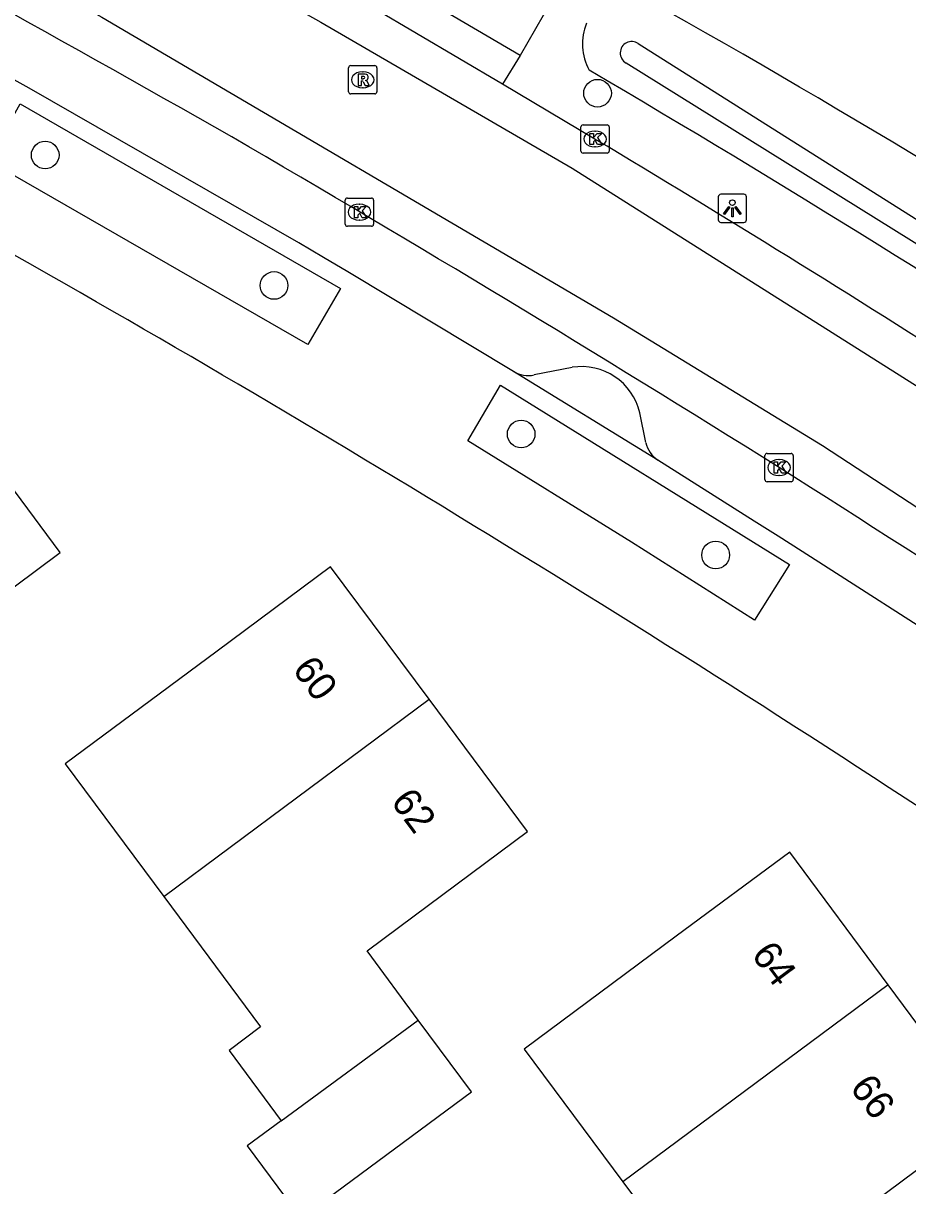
# Model space of a CAD drawing. Extents: x 163427 to 164190, y 380331 to 381641.
# Drawn here: x 163782.5 to 163813.78, y 381420.94 to 381462.05 of the extents above; entities that cross this region are included whole.
import ezdxf

# ---------------------------------------------------------------- set-up
doc = ezdxf.new("R2010")
doc.units = 0
for name, color, linetype in [('IMGEO_Boom', 7, 'Continuous'), ('IMGEO_Erf', 7, 'Continuous'), ('IMGEO_Groenvoorziening', 7, 'Continuous'), ('IMGEO_Kolk', 7, 'Continuous'), ('IMGEO_Lichtpunt', 7, 'Continuous'), ('IMGEO_Pand', 7, 'Continuous'), ('IMGEO_Pand_nummerreeks', 7, 'Continuous'), ('IMGEO_Parkeervlak_open', 7, 'Continuous'), ('IMGEO_Rijbaan_lokaal_gesloten', 7, 'Continuous'), ('IMGEO_Rioolput', 7, 'Continuous'), ('IMGEO_Voetpad_open', 7, 'Continuous'), ('IMGEO_Waterloop', 7, 'Continuous')]:
    doc.layers.add(name, color=color, linetype=linetype)

msp = doc.modelspace()

# ---------------------------------------------------------------- linework, layer by layer
at = {"layer": 'IMGEO_Boom'}
for centre in [(163802.812, 381459.577), (163783.277, 381457.389), (163791.372, 381452.777), (163800.112, 381447.522), (163806.993, 381443.245)]:
    msp.add_circle(centre, 0.489, dxfattribs=at)
at = {"layer": 'IMGEO_Erf'}
msp.add_arc((163640.93, 381170.85), 334.754, 52.44952, 60.85561, dxfattribs=at)
at = {"layer": 'IMGEO_Groenvoorziening'}
for centre, radius, start, end in [((163804.191, 381461.318), 1.915, 157.4819, 208.9313), ((163567.483, 381059.804), 464.446, 53.7231, 59.59903)]:
    msp.add_arc(centre, radius, start, end, dxfattribs=at)
at = {"layer": 'IMGEO_Kolk'}
for p, q in [((163802.224, 381457.531), (163802.224, 381458.383)), ((163802.299, 381458.457), (163803.151, 381458.457)), ((163803.225, 381458.383), (163803.225, 381457.531)), ((163802.712, 381458.237), (163802.737, 381458.237)), ((163802.735, 381457.677), (163802.71, 381457.677)), ((163803.151, 381457.457), (163802.299, 381457.457)), ((163793.892, 381454.944), (163793.892, 381455.796)), ((163793.967, 381455.87), (163794.819, 381455.87)), ((163794.38, 381455.65), (163794.405, 381455.65)), ((163794.893, 381455.796), (163794.893, 381454.944)), ((163794.403, 381455.09), (163794.378, 381455.09)), ((163794.819, 381454.87), (163793.967, 381454.87)), ((163808.734, 381445.912), (163808.734, 381446.764)), ((163808.809, 381446.838), (163809.661, 381446.838)), ((163809.222, 381446.618), (163809.247, 381446.618)), ((163809.735, 381446.764), (163809.735, 381445.912)), ((163809.245, 381446.058), (163809.22, 381446.058)), ((163809.661, 381445.838), (163808.809, 381445.838))]:
    msp.add_line(p, q, dxfattribs=at)
for points in [[(163802.224, 381457.531), (163802.224, 381458.383)], [(163802.299, 381458.457), (163803.151, 381458.457)], [(163803.225, 381458.383), (163803.225, 381457.531)], [(163802.545, 381458.157), (163802.668, 381458.157), (163802.668, 381458.006), (163802.798, 381458.157), (163802.962, 381458.157), (163802.816, 381458.006), (163802.969, 381457.757), (163802.817, 381457.757), (163802.732, 381457.921), (163802.668, 381457.854), (163802.668, 381457.757), (163802.545, 381457.757), (163802.545, 381458.157)], [(163803.151, 381457.457), (163802.299, 381457.457)], [(163793.892, 381454.944), (163793.892, 381455.796)], [(163793.967, 381455.87), (163794.819, 381455.87)], [(163794.213, 381455.57), (163794.336, 381455.57), (163794.336, 381455.419), (163794.466, 381455.57), (163794.63, 381455.57), (163794.484, 381455.419), (163794.637, 381455.17), (163794.485, 381455.17), (163794.4, 381455.334), (163794.336, 381455.267), (163794.336, 381455.17), (163794.213, 381455.17), (163794.213, 381455.57)], [(163794.893, 381455.796), (163794.893, 381454.944)], [(163794.819, 381454.87), (163793.967, 381454.87)], [(163808.734, 381445.912), (163808.734, 381446.764)], [(163808.809, 381446.838), (163809.661, 381446.838)], [(163809.055, 381446.538), (163809.178, 381446.538), (163809.178, 381446.387), (163809.308, 381446.538), (163809.472, 381446.538), (163809.326, 381446.387), (163809.479, 381446.138), (163809.327, 381446.138), (163809.242, 381446.302), (163809.178, 381446.235), (163809.178, 381446.138), (163809.055, 381446.138), (163809.055, 381446.538)], [(163809.735, 381446.764), (163809.735, 381445.912)], [(163809.661, 381445.838), (163808.809, 381445.838)]]:
    msp.add_lwpolyline(points, dxfattribs=at)
for centre, start, end in [((163802.301, 381458.381), 91.552, 178.448), ((163802.301, 381458.381), 91.552, 178.448), ((163803.149, 381458.381), 1.552, 88.448), ((163803.149, 381458.381), 1.552, 88.448), ((163802.301, 381457.533), 181.552, 268.448), ((163802.301, 381457.533), 181.552, 268.448), ((163803.149, 381457.533), 271.552, 358.448), ((163803.149, 381457.533), 271.552, 358.448), ((163793.969, 381455.794), 91.552, 178.448), ((163793.969, 381455.794), 91.552, 178.448), ((163794.817, 381455.794), 1.552, 88.448), ((163794.817, 381455.794), 1.552, 88.448), ((163793.969, 381454.946), 181.552, 268.448), ((163793.969, 381454.946), 181.552, 268.448), ((163794.817, 381454.946), 271.552, 358.448), ((163794.817, 381454.946), 271.552, 358.448), ((163808.811, 381446.762), 91.552, 178.448), ((163808.811, 381446.762), 91.552, 178.448), ((163809.659, 381446.762), 1.552, 88.448), ((163809.659, 381446.762), 1.552, 88.448), ((163808.811, 381445.914), 181.552, 268.448), ((163808.811, 381445.914), 181.552, 268.448), ((163809.659, 381445.914), 271.552, 358.448), ((163809.659, 381445.914), 271.552, 358.448)]:
    msp.add_arc(centre, 0.0765, start, end, dxfattribs=at)
for centre, major_axis, ratio, start_param, end_param in [((163802.711, 381457.957), (-0.387, 0.002), 0.722429, 4.712389, 7.853982), ((163802.736, 381457.957), (-0.39, 0.002), 0.717154, 1.570796, 4.712389), ((163794.379, 381455.37), (-0.387, 0.002), 0.722429, 4.712389, 7.853982), ((163794.404, 381455.37), (-0.39, 0.002), 0.717154, 1.570796, 4.712389), ((163809.221, 381446.338), (-0.387, 0.002), 0.722429, 4.712389, 7.853982), ((163809.246, 381446.338), (-0.39, 0.002), 0.717154, 1.570796, 4.712389)]:
    msp.add_ellipse(centre, major_axis=major_axis, ratio=ratio, start_param=start_param, end_param=end_param, dxfattribs=at)
at = {"layer": 'IMGEO_Lichtpunt'}
for p, q in [((163807.084, 381455.909), (163807.084, 381455.102)), ((163807.084, 381455.909), (163807.084, 381455.102)), ((163807.986, 381456.004), (163807.178, 381456.004)), ((163807.986, 381456.004), (163807.178, 381456.004)), ((163808.08, 381455.102), (163808.08, 381455.909)), ((163808.08, 381455.102), (163808.08, 381455.909)), ((163807.178, 381455.008), (163807.986, 381455.008)), ((163807.178, 381455.008), (163807.986, 381455.008))]:
    msp.add_line(p, q, dxfattribs=at)
for points in [[(163807.458, 381455.573), (163807.497, 381455.545), (163807.309, 381455.283), (163807.271, 381455.31), (163807.458, 381455.573)], [(163807.56, 381455.525), (163807.607, 381455.525), (163807.607, 381455.203), (163807.56, 381455.203), (163807.56, 381455.525)], [(163807.67, 381455.545), (163807.708, 381455.572), (163807.895, 381455.31), (163807.856, 381455.282), (163807.67, 381455.545)]]:
    msp.add_lwpolyline(points, dxfattribs=at)
msp.add_circle((163807.583, 381455.707), 0.0994, dxfattribs=at)
for centre, start, end in [((163807.178, 381455.909), 90, 180), ((163807.178, 381455.909), 90, 180), ((163807.986, 381455.909), 0, 90), ((163807.986, 381455.909), 0, 90), ((163807.178, 381455.102), 180, 270), ((163807.178, 381455.102), 180, 270), ((163807.986, 381455.102), 270, 0), ((163807.986, 381455.102), 270, 360)]:
    msp.add_arc(centre, 0.0946, start, end, dxfattribs=at)
at = {"layer": 'IMGEO_Pand'}
for points in [[(163780.023, 381436.723), (163778.207, 381439.168), (163779.797, 381440.349), (163783.81, 381443.33), (163780.328, 381448.016)], [(163796.858, 381438.147), (163793.37, 381442.83), (163789.356, 381439.849), (163783.984, 381435.859), (163787.468, 381431.168)], [(163787.468, 381431.168), (163796.858, 381438.147)], [(163796.474, 381426.798), (163794.67, 381429.24), (163796.333, 381430.481), (163800.34, 381433.47), (163796.858, 381438.147)], [(163813.094, 381428.041), (163809.61, 381432.74), (163805.596, 381429.76), (163800.22, 381425.77), (163803.709, 381421.08)], [(163787.468, 381431.168), (163790.896, 381426.553), (163789.781, 381425.725), (163791.628, 381423.238)], [(163813.094, 381428.041), (163803.709, 381421.08)], [(163812.725, 381416.692), (163810.915, 381419.125), (163812.569, 381420.356), (163816.58, 381423.34), (163813.094, 381428.041)], [(163791.628, 381423.238), (163790.425, 381422.344), (163792.32, 381419.79), (163798.35, 381424.26), (163796.474, 381426.798)], [(163791.628, 381423.238), (163796.474, 381426.798)], [(163803.709, 381421.08), (163807.147, 381416.459), (163806.042, 381415.636), (163807.901, 381413.113)]]:
    msp.add_lwpolyline(points, dxfattribs=at)
at = {"layer": 'IMGEO_Parkeervlak_open'}
for points in [[(163801.915, 381449.882), (163800.566, 381449.613)], [(163804.519, 381447.218), (163804.303, 381448.275)]]:
    msp.add_lwpolyline(points, dxfattribs=at)
for centre, radius, start, end in [((163800.361, 381450.638), 1.045, 240.4163, 281.304), ((163802.25, 381447.802), 2.107, 12.9756, 99.1474), ((163805.579, 381447.49), 1.095, 194.4044, 234.7845)]:
    msp.add_arc(centre, radius, start, end, dxfattribs=at)
at = {"layer": 'IMGEO_Rijbaan_lokaal_gesloten'}
for points in [[(163713.873, 381501.243), (163733.236, 381492.736), (163749.22, 381485.298), (163767.31, 381476.496), (163780.878, 381468.904), (163793.021, 381462.086), (163801.914, 381456.926), (163805.316, 381454.777), (163822.941, 381443.637), (163833.227, 381436.556), (163841.848, 381430.533), (163854.116, 381421.564)], [(163712.408, 381497.746), (163724.81, 381492.736), (163743.644, 381483.934), (163766.443, 381472.53), (163780.444, 381464.999), (163785.277, 381462.271), (163803.377, 381451.63), (163810.77, 381447.112), (163827.662, 381436.066), (163844.931, 381423.887), (163862.01, 381410.858), (163868.144, 381405.949), (163877.464, 381398.208), (163891.264, 381386.878), (163901.361, 381378.381), (163902.433, 381377.241), (163901.472, 381376.366)], [(163799.449, 381459.898), (163791.847, 381464.384)], [(163802.72, 381457.956), (163799.449, 381459.898)]]:
    msp.add_lwpolyline(points, dxfattribs=at)
for centre, radius, start, end in [((163344.636, 380676.214), 899.71, 60.338897, 61.743637), ((163449.425, 380872.622), 677.209, 57.906152, 59.819608), ((163529.386, 381001.656), 531.904, 55.62548, 59.07748), ((163490.092, 380940.74), 597.896, 55.713196, 57.739435)]:
    msp.add_arc(centre, radius, start, end, dxfattribs=at)
at = {"layer": 'IMGEO_Rioolput'}
for p, q in [((163794.009, 381459.626), (163794.009, 381460.478)), ((163794.084, 381460.552), (163794.936, 381460.552)), ((163795.01, 381460.478), (163795.01, 381459.626)), ((163794.497, 381460.332), (163794.522, 381460.332)), ((163794.52, 381459.772), (163794.495, 381459.772)), ((163794.936, 381459.552), (163794.084, 381459.552))]:
    msp.add_line(p, q, dxfattribs=at)
for points in [[(163794.009, 381459.626), (163794.009, 381460.478)], [(163794.084, 381460.552), (163794.936, 381460.552)], [(163795.01, 381460.478), (163795.01, 381459.626)], [(163794.598, 381460.25), (163794.346, 381460.252), (163794.346, 381459.852)], [(163794.346, 381459.852), (163794.47, 381459.852), (163794.47, 381460.014), (163794.481, 381460.014)], [(163794.524, 381460.171), (163794.47, 381460.171), (163794.47, 381460.09)], [(163794.47, 381460.09), (163794.522, 381460.09)], [(163794.528, 381459.985), (163794.599, 381459.852), (163794.739, 381459.852), (163794.674, 381459.978)], [(163794.936, 381459.552), (163794.084, 381459.552)]]:
    msp.add_lwpolyline(points, dxfattribs=at)
for centre, radius, start, end in [((163794.086, 381460.476), 0.0765, 91.552, 178.448), ((163794.086, 381460.476), 0.0765, 91.552, 178.448), ((163794.934, 381460.476), 0.0765, 1.552, 88.448), ((163794.934, 381460.476), 0.0765, 1.552, 88.448), ((163794.48, 381459.961), 0.0533, 26.0293, 88.6989), ((163794.506, 381460.279), 0.19, 274.7715, 282.9687), ((163794.53, 381460.075), 0.0964, 77.0061, 93.1865), ((163794.544, 381460.132), 0.0378, 276.6634, 79.6772), ((163794.597, 381460.14), 0.109, 350.3612, 89.416), ((163794.595, 381460.14), 0.112, 277.5842, 350.9817), ((163794.579, 381459.925), 0.108, 29.5134, 73.7905), ((163794.086, 381459.628), 0.0765, 181.552, 268.448), ((163794.086, 381459.628), 0.0765, 181.552, 268.448), ((163794.934, 381459.628), 0.0765, 271.552, 358.448), ((163794.934, 381459.628), 0.0765, 271.552, 358.448)]:
    msp.add_arc(centre, radius, start, end, dxfattribs=at)
for centre, major_axis, ratio, start_param, end_param in [((163794.496, 381460.052), (-0.387, 0.002), 0.722429, 4.712389, 7.853982), ((163794.521, 381460.052), (-0.39, 0.002), 0.717154, 1.570796, 4.712389)]:
    msp.add_ellipse(centre, major_axis=major_axis, ratio=ratio, start_param=start_param, end_param=end_param, dxfattribs=at)
at = {"layer": 'IMGEO_Voetpad_open'}
for points in [[(163799.845, 381449.729), (163793.982, 381453.254), (163793.115, 381453.768), (163792.247, 381454.28), (163782.711, 381459.759), (163776.754, 381463.062), (163765.24, 381469.221), (163759.164, 381472.317), (163747.09, 381478.292), (163740.938, 381481.248)], [(163800.076, 381460.909), (163792.446, 381465.386)], [(163802.031, 381464.312), (163801.162, 381462.8), (163800.076, 381460.909)], [(163800.076, 381460.909), (163799.449, 381459.898)], [(163792.566, 381450.689), (163781.265, 381457.187), (163782.392, 381459.206), (163793.724, 381452.667), (163792.566, 381450.689)], [(163804.948, 381446.596), (163799.845, 381449.729)], [(163808.37, 381440.94), (163804.012, 381443.699), (163798.228, 381447.277), (163799.378, 381449.25), (163809.607, 381442.906), (163808.37, 381440.94)], [(163831.598, 381429.033), (163825.973, 381432.889), (163824.978, 381433.571), (163815.786, 381439.691), (163810.052, 381443.37), (163809.2, 381443.908), (163808.347, 381444.444), (163804.948, 381446.596)]]:
    msp.add_lwpolyline(points, dxfattribs=at)
for centre, radius, start, end in [((163514.222, 380980.216), 544.183, 58.44928, 60.6261), ((163511.009, 380972.313), 552.6, 56.37047, 58.59412)]:
    msp.add_arc(centre, radius, start, end, dxfattribs=at)
at = {"layer": 'IMGEO_Waterloop'}
for points in [[(163804.255, 381461.336), (163821.698, 381450.307), (163843.997, 381435.276)], [(163843.659, 381434.68), (163817.036, 381452.411), (163803.823, 381460.644)]]:
    msp.add_lwpolyline(points, dxfattribs=at)
msp.add_arc((163804.024, 381460.999), 0.408, 55.6035, 240.4452, dxfattribs=at)

# ---------------------------------------------------------------- texts
at = {"layer": 'IMGEO_Pand_nummerreeks'}
for s, rotation, p in [('60', 306.6735, (163791.991, 381439.191)), ('62', 306.6735, (163795.472, 381434.516)), ('64', 306.5565, (163808.225, 381429.101)), ('66', 306.5565, (163811.71, 381424.401))]:
    msp.add_text(s, height=1, rotation=rotation, dxfattribs=at).set_placement(p)

doc.saveas('drawing.dxf')
